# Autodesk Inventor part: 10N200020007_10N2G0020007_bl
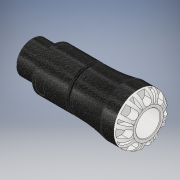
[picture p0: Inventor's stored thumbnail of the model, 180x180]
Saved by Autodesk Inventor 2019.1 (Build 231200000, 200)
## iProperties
Created: 2016-12
Part Number: 10N200020007_10N2G0020007_bl
Material: PVC-Piping
Description: PLASSON MALE ADAPTOR 20X3/4" SERIES 1
Document SubType Name: Modeling
Designer: KIM
Mass: 61.7504 g
Surface Area: 140.097 cm^2
Volume: 44.1074 cm^3
Density: 1.4 g/cm^3
Appearance: Black Cast
Author: KIM
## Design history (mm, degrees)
derived "10N20.ipt"
feature "Solid1::10N20.ipt" dims "ScaleForDerivedMember" = 10
tag "TaggingFeature1"
body "Solid1"
other parameters: "d0" = 96 [user parameter], "d1" = 18.9 [user parameter], "d3" = 25 [user parameter], "d4" = 41 [user parameter], "d6" = 45 [user parameter], "d8" = 34.85 [user parameter], "d13" = 6.4 [user parameter], "d14" = 6.4 [user parameter], "d15" = 0 [user parameter], "d17" = 360 deg [user parameter], "d19" = 8 deg [user parameter], "d20" = 0.4 [user parameter], "d21" = 0.4 [user parameter], "d22" = 8 deg [user parameter], "d24" = 0 [user parameter], "d26" = 360 deg [user parameter], "d32" = 0.925 [user parameter], "d33" = 4.1 [user parameter], "d34" = 26.441 [user parameter], "d35" = 2.5 [user parameter], "d38" = 17 [user parameter], "d39" = 0.79323 [user parameter], "d42" = 7 [user parameter], "d43" = 4.6 [user parameter], "d45" = 12.544 [user parameter], "d46" = 0 [user parameter], "d59" = 360 deg [user parameter], "d61" = 5.95 [user parameter], "d62" = 0.4 [user parameter], "d64" = 0 [user parameter], "d65" = 0.41 [user parameter], "d69" = 2 [user parameter], "d70" = 1.44 [user parameter], "d71" = 3 [user parameter], "d73" = 1 [user parameter], "E_" = 41 [user parameter], "H_" = 96 [user parameter], "l_" = 45 [user parameter], "R_" = 26.441 [user parameter], "l_2" = 17 [user parameter], "d9" = 8 [user parameter], "d11" = 41 [user parameter], "d12" = 25 [user parameter]
